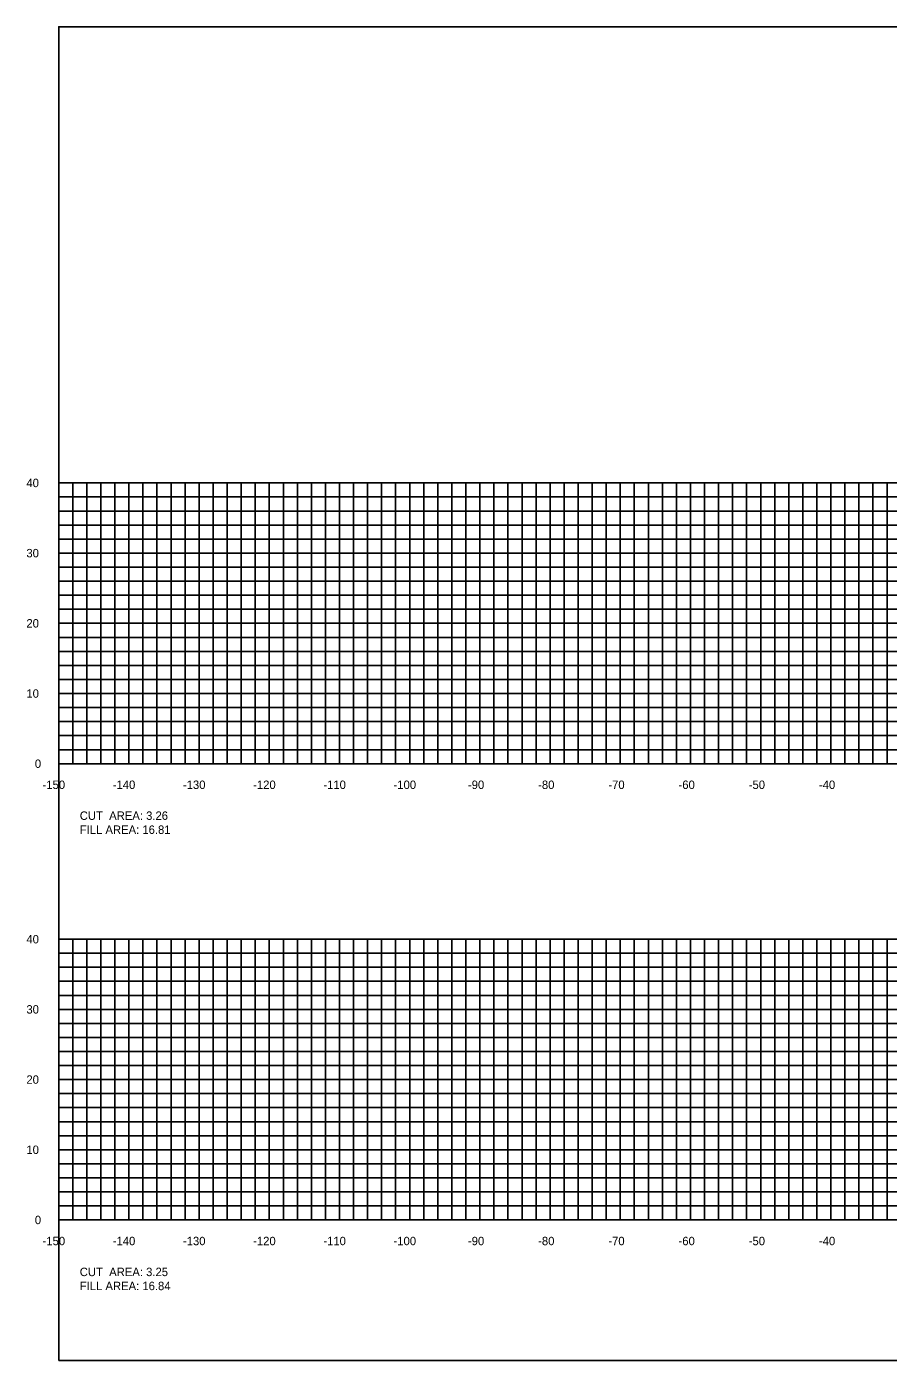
# Model space of a CAD drawing. Extents: x 1797645 to 1803805, y 248417 to 250269.
# Drawn here: x 1802816.4 to 1802939.2, y 250079.4 to 250269.4 of the extents above; entities that cross this region are included whole.
import ezdxf

# ---------------------------------------------------------------- set-up
doc = ezdxf.new("R2010")
doc.units = 0
for name, color, linetype in [('10', 7, 'Continuous'), ('31', 7, 'Continuous'), ('60', 7, 'Continuous'), ('ANNO-TXT', 7, 'Continuous'), ('Level 62', 7, 'Continuous')]:
    doc.layers.add(name, color=color, linetype=linetype)

msp = doc.modelspace()

# ---------------------------------------------------------------- linework, layer by layer
msp.add_lwpolyline([(1802821, 250079.43), (1803121, 250079.43), (1803121, 250269.43), (1802821, 250269.43)], close=True)
at = {"layer": '60'}
for p, q in [((1802820.94, 250204.43), (1802821, 250204.43)), ((1802821, 250164.43), (1802821, 250204.43)), ((1802820.94, 250194.43), (1802821, 250194.43)), ((1802820.94, 250184.43), (1802821, 250184.43)), ((1802820.94, 250174.43), (1802821, 250174.43)), ((1802820.94, 250164.43), (1802821, 250164.43)), ((1802821, 250164.43), (1803121, 250164.43)), ((1802821, 250164.37), (1802821, 250164.43)), ((1802831, 250164.37), (1802831, 250164.43)), ((1802841, 250164.37), (1802841, 250164.43)), ((1802851, 250164.37), (1802851, 250164.43)), ((1802861, 250164.37), (1802861, 250164.43)), ((1802871, 250164.37), (1802871, 250164.43)), ((1802881, 250164.37), (1802881, 250164.43)), ((1802891, 250164.37), (1802891, 250164.43)), ((1802901, 250164.37), (1802901, 250164.43)), ((1802911, 250164.37), (1802911, 250164.43)), ((1802921, 250164.37), (1802921, 250164.43)), ((1802931, 250164.37), (1802931, 250164.43)), ((1802820.94, 250139.43), (1802821, 250139.43)), ((1802821, 250099.43), (1802821, 250139.43)), ((1802820.94, 250129.43), (1802821, 250129.43)), ((1802820.94, 250119.43), (1802821, 250119.43)), ((1802820.94, 250109.43), (1802821, 250109.43)), ((1802820.94, 250099.43), (1802821, 250099.43)), ((1802821, 250099.43), (1803121, 250099.43)), ((1802821, 250099.37), (1802821, 250099.43)), ((1802831, 250099.37), (1802831, 250099.43)), ((1802841, 250099.37), (1802841, 250099.43)), ((1802851, 250099.37), (1802851, 250099.43)), ((1802861, 250099.37), (1802861, 250099.43)), ((1802871, 250099.37), (1802871, 250099.43)), ((1802881, 250099.37), (1802881, 250099.43)), ((1802891, 250099.37), (1802891, 250099.43)), ((1802901, 250099.37), (1802901, 250099.43)), ((1802911, 250099.37), (1802911, 250099.43)), ((1802921, 250099.37), (1802921, 250099.43)), ((1802931, 250099.37), (1802931, 250099.43))]:
    msp.add_line(p, q, dxfattribs=at)
at = {"layer": 'Level 62'}
for p, q in [((1802821, 250204.43), (1803121, 250204.43)), ((1802821, 250164.43), (1802821, 250204.43)), ((1802823, 250164.43), (1802823, 250204.43)), ((1802825, 250164.43), (1802825, 250204.43)), ((1802827, 250164.43), (1802827, 250204.43)), ((1802829, 250164.43), (1802829, 250204.43)), ((1802831, 250164.43), (1802831, 250204.43)), ((1802833, 250164.43), (1802833, 250204.43)), ((1802835, 250164.43), (1802835, 250204.43)), ((1802837, 250164.43), (1802837, 250204.43)), ((1802839, 250164.43), (1802839, 250204.43)), ((1802841, 250164.43), (1802841, 250204.43)), ((1802843, 250164.43), (1802843, 250204.43)), ((1802845, 250164.43), (1802845, 250204.43)), ((1802847, 250164.43), (1802847, 250204.43)), ((1802849, 250164.43), (1802849, 250204.43)), ((1802851, 250164.43), (1802851, 250204.43)), ((1802853, 250164.43), (1802853, 250204.43)), ((1802855, 250164.43), (1802855, 250204.43)), ((1802857, 250164.43), (1802857, 250204.43)), ((1802859, 250164.43), (1802859, 250204.43)), ((1802861, 250164.43), (1802861, 250204.43)), ((1802863, 250164.43), (1802863, 250204.43)), ((1802865, 250164.43), (1802865, 250204.43)), ((1802867, 250164.43), (1802867, 250204.43)), ((1802869, 250164.43), (1802869, 250204.43)), ((1802871, 250164.43), (1802871, 250204.43)), ((1802873, 250164.43), (1802873, 250204.43)), ((1802875, 250164.43), (1802875, 250204.43)), ((1802877, 250164.43), (1802877, 250204.43)), ((1802879, 250164.43), (1802879, 250204.43)), ((1802881, 250164.43), (1802881, 250204.43)), ((1802883, 250164.43), (1802883, 250204.43)), ((1802885, 250164.43), (1802885, 250204.43)), ((1802887, 250164.43), (1802887, 250204.43)), ((1802889, 250164.43), (1802889, 250204.43)), ((1802891, 250164.43), (1802891, 250204.43)), ((1802893, 250164.43), (1802893, 250204.43)), ((1802895, 250164.43), (1802895, 250204.43)), ((1802897, 250164.43), (1802897, 250204.43)), ((1802899, 250164.43), (1802899, 250204.43)), ((1802901, 250164.43), (1802901, 250204.43)), ((1802903, 250164.43), (1802903, 250204.43)), ((1802905, 250164.43), (1802905, 250204.43)), ((1802907, 250164.43), (1802907, 250204.43)), ((1802909, 250164.43), (1802909, 250204.43)), ((1802911, 250164.43), (1802911, 250204.43)), ((1802913, 250164.43), (1802913, 250204.43)), ((1802915, 250164.43), (1802915, 250204.43)), ((1802917, 250164.43), (1802917, 250204.43)), ((1802919, 250164.43), (1802919, 250204.43)), ((1802921, 250164.43), (1802921, 250204.43)), ((1802923, 250164.43), (1802923, 250204.43)), ((1802925, 250164.43), (1802925, 250204.43)), ((1802927, 250164.43), (1802927, 250204.43)), ((1802929, 250164.43), (1802929, 250204.43)), ((1802931, 250164.43), (1802931, 250204.43)), ((1802933, 250164.43), (1802933, 250204.43)), ((1802935, 250164.43), (1802935, 250204.43)), ((1802937, 250164.43), (1802937, 250204.43)), ((1802939, 250164.43), (1802939, 250204.43)), ((1802821, 250202.43), (1803121, 250202.43)), ((1802821, 250200.43), (1803121, 250200.43)), ((1802821, 250198.43), (1803121, 250198.43)), ((1802821, 250196.43), (1803121, 250196.43)), ((1802821, 250194.43), (1803121, 250194.43)), ((1802821, 250192.43), (1803121, 250192.43)), ((1802821, 250190.43), (1803121, 250190.43)), ((1802821, 250188.43), (1803121, 250188.43)), ((1802821, 250186.43), (1803121, 250186.43)), ((1802821, 250184.43), (1803121, 250184.43)), ((1802821, 250182.43), (1803121, 250182.43)), ((1802821, 250180.43), (1803121, 250180.43)), ((1802821, 250178.43), (1803121, 250178.43)), ((1802821, 250176.43), (1803121, 250176.43)), ((1802821, 250174.43), (1803121, 250174.43)), ((1802821, 250172.43), (1803121, 250172.43)), ((1802821, 250170.43), (1803121, 250170.43)), ((1802821, 250168.43), (1803121, 250168.43)), ((1802821, 250166.43), (1803121, 250166.43)), ((1802821, 250164.43), (1803121, 250164.43)), ((1802821, 250139.43), (1803121, 250139.43)), ((1802821, 250099.43), (1802821, 250139.43)), ((1802823, 250099.43), (1802823, 250139.43)), ((1802825, 250099.43), (1802825, 250139.43)), ((1802827, 250099.43), (1802827, 250139.43)), ((1802829, 250099.43), (1802829, 250139.43)), ((1802831, 250099.43), (1802831, 250139.43)), ((1802833, 250099.43), (1802833, 250139.43)), ((1802835, 250099.43), (1802835, 250139.43)), ((1802837, 250099.43), (1802837, 250139.43)), ((1802839, 250099.43), (1802839, 250139.43)), ((1802841, 250099.43), (1802841, 250139.43)), ((1802843, 250099.43), (1802843, 250139.43)), ((1802845, 250099.43), (1802845, 250139.43)), ((1802847, 250099.43), (1802847, 250139.43)), ((1802849, 250099.43), (1802849, 250139.43)), ((1802851, 250099.43), (1802851, 250139.43)), ((1802853, 250099.43), (1802853, 250139.43)), ((1802855, 250099.43), (1802855, 250139.43)), ((1802857, 250099.43), (1802857, 250139.43)), ((1802859, 250099.43), (1802859, 250139.43)), ((1802861, 250099.43), (1802861, 250139.43)), ((1802863, 250099.43), (1802863, 250139.43)), ((1802865, 250099.43), (1802865, 250139.43)), ((1802867, 250099.43), (1802867, 250139.43)), ((1802869, 250099.43), (1802869, 250139.43)), ((1802871, 250099.43), (1802871, 250139.43)), ((1802873, 250099.43), (1802873, 250139.43)), ((1802875, 250099.43), (1802875, 250139.43)), ((1802877, 250099.43), (1802877, 250139.43)), ((1802879, 250099.43), (1802879, 250139.43)), ((1802881, 250099.43), (1802881, 250139.43)), ((1802883, 250099.43), (1802883, 250139.43)), ((1802885, 250099.43), (1802885, 250139.43)), ((1802887, 250099.43), (1802887, 250139.43)), ((1802889, 250099.43), (1802889, 250139.43)), ((1802891, 250099.43), (1802891, 250139.43)), ((1802893, 250099.43), (1802893, 250139.43)), ((1802895, 250099.43), (1802895, 250139.43)), ((1802897, 250099.43), (1802897, 250139.43)), ((1802899, 250099.43), (1802899, 250139.43)), ((1802901, 250099.43), (1802901, 250139.43)), ((1802903, 250099.43), (1802903, 250139.43)), ((1802905, 250099.43), (1802905, 250139.43)), ((1802907, 250099.43), (1802907, 250139.43)), ((1802909, 250099.43), (1802909, 250139.43)), ((1802911, 250099.43), (1802911, 250139.43)), ((1802913, 250099.43), (1802913, 250139.43)), ((1802915, 250099.43), (1802915, 250139.43)), ((1802917, 250099.43), (1802917, 250139.43)), ((1802919, 250099.43), (1802919, 250139.43)), ((1802921, 250099.43), (1802921, 250139.43)), ((1802923, 250099.43), (1802923, 250139.43)), ((1802925, 250099.43), (1802925, 250139.43)), ((1802927, 250099.43), (1802927, 250139.43)), ((1802929, 250099.43), (1802929, 250139.43)), ((1802931, 250099.43), (1802931, 250139.43)), ((1802933, 250099.43), (1802933, 250139.43)), ((1802935, 250099.43), (1802935, 250139.43)), ((1802937, 250099.43), (1802937, 250139.43)), ((1802939, 250099.43), (1802939, 250139.43)), ((1802821, 250137.43), (1803121, 250137.43)), ((1802821, 250135.43), (1803121, 250135.43)), ((1802821, 250133.43), (1803121, 250133.43)), ((1802821, 250131.43), (1803121, 250131.43)), ((1802821, 250129.43), (1803121, 250129.43)), ((1802821, 250127.43), (1803121, 250127.43)), ((1802821, 250125.43), (1803121, 250125.43)), ((1802821, 250123.43), (1803121, 250123.43)), ((1802821, 250121.43), (1803121, 250121.43)), ((1802821, 250119.43), (1803121, 250119.43)), ((1802821, 250117.43), (1803121, 250117.43)), ((1802821, 250115.43), (1803121, 250115.43)), ((1802821, 250113.43), (1803121, 250113.43)), ((1802821, 250111.43), (1803121, 250111.43)), ((1802821, 250109.43), (1803121, 250109.43)), ((1802821, 250107.43), (1803121, 250107.43)), ((1802821, 250105.43), (1803121, 250105.43)), ((1802821, 250103.43), (1803121, 250103.43)), ((1802821, 250101.43), (1803121, 250101.43)), ((1802821, 250099.43), (1803121, 250099.43))]:
    msp.add_line(p, q, dxfattribs=at)

# ---------------------------------------------------------------- texts
at = {"layer": '10'}
for s, p in [('-150', (1802818.7, 250160.83)), ('-140', (1802828.7, 250160.83)), ('-130', (1802838.7, 250160.83)), ('-120', (1802848.7, 250160.83)), ('-110', (1802858.7, 250160.83)), ('-100', (1802868.7, 250160.83)), ('-90', (1802879.3, 250160.83)), ('-80', (1802889.3, 250160.83)), ('-70', (1802899.3, 250160.83)), ('-60', (1802909.3, 250160.83)), ('-50', (1802919.3, 250160.83)), ('-40', (1802929.3, 250160.83)), ('-150', (1802818.7, 250095.83)), ('-140', (1802828.7, 250095.83)), ('-130', (1802838.7, 250095.83)), ('-120', (1802848.7, 250095.83)), ('-110', (1802858.7, 250095.83)), ('-100', (1802868.7, 250095.83)), ('-90', (1802879.3, 250095.83)), ('-80', (1802889.3, 250095.83)), ('-70', (1802899.3, 250095.83)), ('-60', (1802909.3, 250095.83)), ('-50', (1802919.3, 250095.83)), ('-40', (1802929.3, 250095.83))]:
    msp.add_text(s, height=1.2, dxfattribs=at).set_placement(p)
at = {"layer": '31'}
for s, p in [('40', (1802816.4, 250203.83)), ('30', (1802816.4, 250193.83)), ('20', (1802816.4, 250183.83)), ('10', (1802816.4, 250173.83)), ('0', (1802817.6, 250163.83)), ('40', (1802816.4, 250138.83)), ('30', (1802816.4, 250128.83)), ('20', (1802816.4, 250118.83)), ('10', (1802816.4, 250108.83)), ('0', (1802817.6, 250098.83))]:
    msp.add_text(s, height=1.2, dxfattribs=at).set_placement(p)
at = {"layer": '60'}
for p in [(1802821, 250164.43), (1802821, 250099.43)]:
    msp.add_text('-', height=0.0001, dxfattribs=at).set_placement(p)
at = {"layer": 'ANNO-TXT'}
for s, p in [('CUT  AREA: 3.26', (1802824, 250156.43)), ('FILL AREA: 16.81', (1802824, 250154.43)), ('CUT  AREA: 3.25', (1802824, 250091.43)), ('FILL AREA: 16.84', (1802824, 250089.43))]:
    msp.add_text(s, height=1.2, dxfattribs=at).set_placement(p)

doc.saveas('drawing.dxf')
